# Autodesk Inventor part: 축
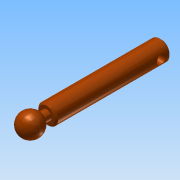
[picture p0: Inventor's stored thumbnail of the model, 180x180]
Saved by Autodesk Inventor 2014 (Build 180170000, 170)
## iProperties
Created: 2017-10
Part Number: 축
Material: 강철, 연강
Document SubType Name: Modeling
Designer: mduedu
Density: 7.86 g/cm^3
Mass: 72.1688 g
Surface Area: 35.8526 cm^2
Volume: 9.18179 cm^3
Appearance: 매끄러움 - 연한 주황색
Author: mduedu
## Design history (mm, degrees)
sketch "스케치1"
  geometry: C1 r 6 at (0, 0); 1 further point
  constraints: 1 centre point, 1 coincident
  dimensions: "d0" = 12 diameter of C1
extrude "돌출1" new body sketch "스케치1" distance "d1" = 70; taper "d2" = 0 deg
sketch "스케치2"
  geometry: L1 (7, 80)-(-7, 80); L2 (6, 70)-(-6, 70) reference; A1 r 7 centre (0, 80) between (7, 80) and (-7, 80); 2 further points
  constraints: 2 end point, 2 midpoint, 2 point on circle, 1 centre point, 1 horizontal, 1 vertical alignment
  dimensions: "d3" = 14 diameter of A1; "d5" = 10 distance from line of L2 A1.centre
revolve "회전1" sketch "스케치2" stored, may be unused: angle "d4" = 90 deg
sketch "스케치3"
  geometry: C1 r 3 at (0, 0); 1 further point
  constraints: 1 centre point, 1 coincident
  dimensions: "d6" = 6 diameter of C1
extrude "돌출2" join sketch "스케치3" stored distance "d7" = 70; taper "d8" = 0 deg
chamfer "모따기1" distance "d9" = 1; stored, may be unused: second distance "d10" = 2, angle "d11" = 45 deg
sketch "스케치4"
  geometry: C1 r 2.5 at (0, 6); 1 further point
  constraints: 1 centre point, 1 vertical alignment
  dimensions: "d12" = 5 diameter of C1; "d13" = 6 distance of point (0, 0) C1.centre
extrude "돌출3" cut sketch "스케치4" stored distance "d14" = 70; taper "d15" = 0 deg
sketch "스케치6"
  geometry: A1 r 7 centre (0, 80) between (3, 73.675) and (-3, 73.675) reference; 2 further points
  constraints: 1 coincident
node "작업점1"
node "솔리드1"
